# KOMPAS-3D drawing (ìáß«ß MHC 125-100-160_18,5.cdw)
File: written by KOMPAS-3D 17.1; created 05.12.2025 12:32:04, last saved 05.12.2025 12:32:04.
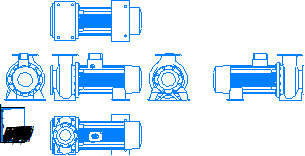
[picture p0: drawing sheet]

Sheet 1: A4, portrait

Title block, sheet 1: name: Насос MHC / 125-100-160_18,5 18,5 кВт / 3х380В; material: Сталь 10  ГОСТ 1050-88; mass: 326,95; sheets: 1; sheet format: A4

Views: Проекционный вид 2, Проекционный вид 3, Проекционный вид 4, Проекционный вид 5, Проекционный вид 6
Referenced files in \\adlc.lan\data\АДЛ_ПКД\3D-модели\ADL production\Насосы ГРАНПАМП\Насосы ГРАНПАМП серии МНС\KOMPAS 3D\: Насос MHC 125-100-160_18,5.m3d
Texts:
  Andrey
  АДЛ
Dimensions and other numbers on the sheet: 1:1; 1; 3х380В; 326,95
